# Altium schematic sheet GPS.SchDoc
size A3
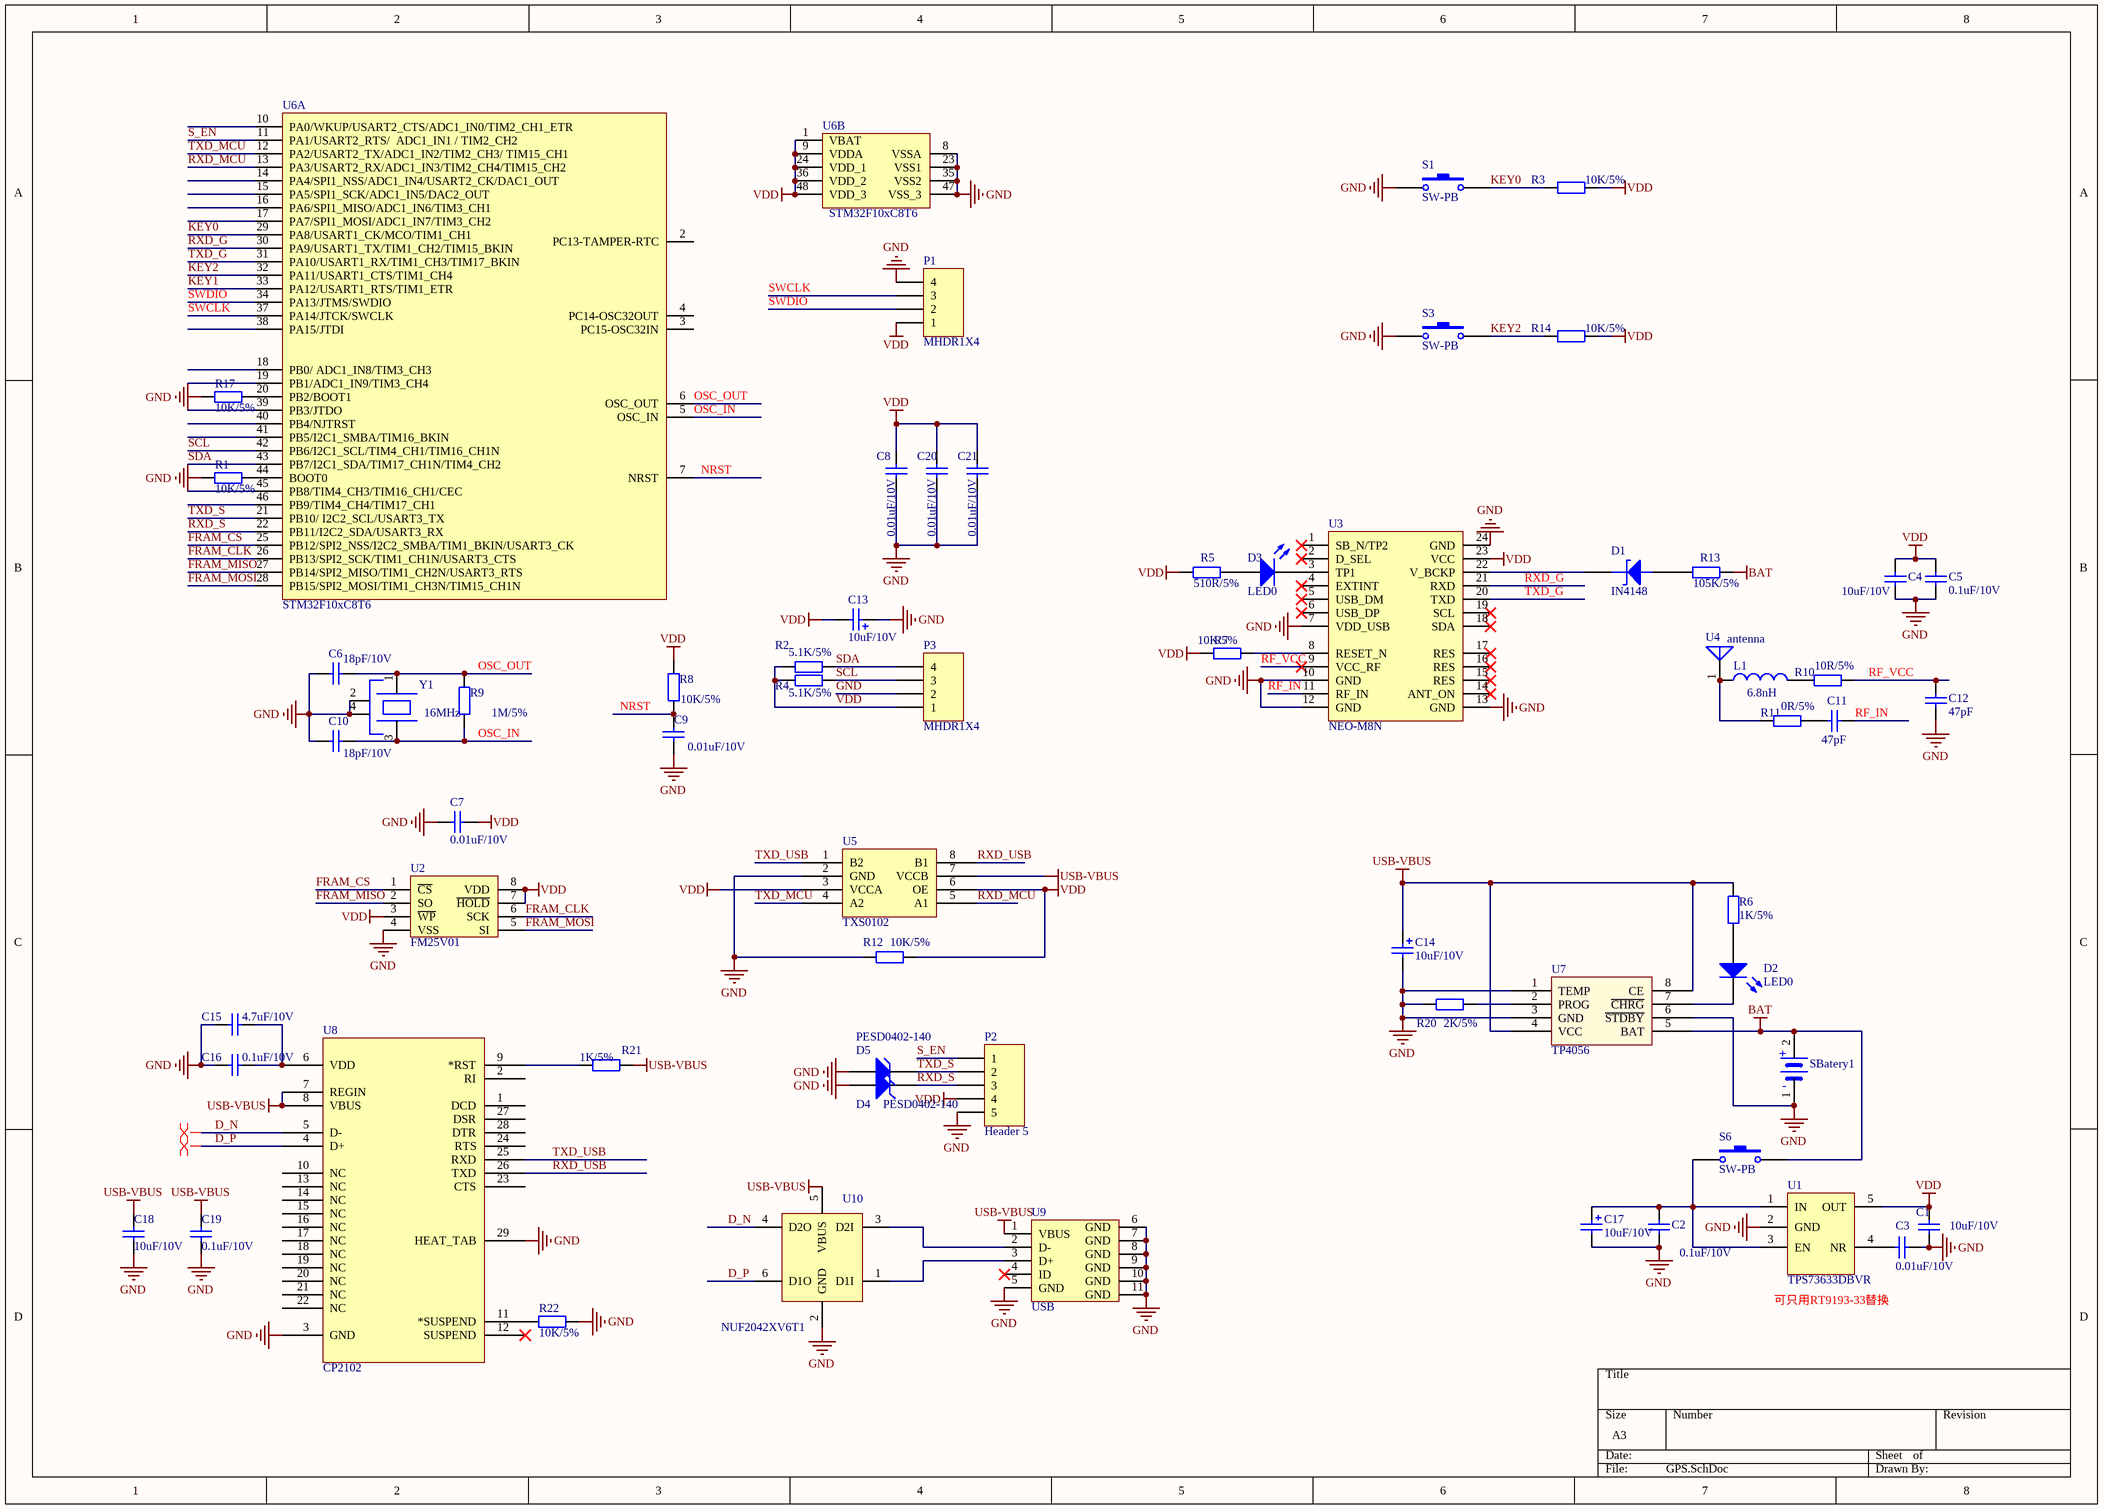
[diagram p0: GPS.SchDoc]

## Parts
C1  10uF/10V  [C0603]
C2  0.1uF/10V  [C0402]
C3  0.01uF/10V  [C0402]
C4  10uF/10V  [3528]
C5  0.1uF/10V  [C0402]
C6  18pF/10V  [C0402]
C7  0.01uF/10V  [C0402]
C8  0.01uF/10V  [C0402]
C9  0.01uF/10V  [C0402]
C10  18pF/10V  [C0402]
C11  value 47pF  [C0402]  (hidden comment: 470pF)
C12  value 47pF  [C0402]  (hidden comment: 33nF)
C13  10uF/10V  [C1206]
C14  10uF/10V  [3528]
C15  4.7uF/10V  [C0603]
C16  0.1uF/10V  [C0402]
C17  10uF/10V  [3528]
C18  10uF/10V  [C0603]
C19  0.1uF/10V  [C0402]
C20  0.01uF/10V  [C0402]
C21  0.01uF/10V  [C0402]
D1  IN4148  [L1206]
D2  LED0  [LED0603]
D3  LED0  [LED0603]
D4  PESD0402-140  [0402-TVS]
D5  PESD0402-140  [0402-TVS]
L1  6.8nH  [R0603]
P1  MHDR1X4  [SIP4_1.27]
P2  Header 5  [HDR1X5]
P3  MHDR1X4  [OLED]
R1  10K/5%  [R0402]
R2  5.1K/5%  [R0402]
R3  10K/5%  [R0402]
R4  5.1K/5%  [R0402]
R5  510R/5%  [R0402]
R6  1K/5%  [R0402]
R7  10K/5%  [R0402]
R8  10K/5%  [R0402]
R9  1M/5%  [R0402]
R10  10R/5%  [R0402]
R11  0R/5%  [R0402]
R12  10K/5%  [R0402]
R13  105K/5%  [R0402]
R14  10K/5%  [R0402]
R17  10K/5%  [R0402]
R20  2K/5%  [R0402]
R21  1K/5%  [R0402]
R22  10K/5%  [R0402]
S1  SW-PB  [KEY2]
S3  SW-PB  [KEY2]
S6  SW-PB  [KEY1]
SBatery1  SBatery  [SIP2]  (value not drawn)
U1  TPS73633DBVR  [SOP5-TPS73633DBVR]
U2  FM25V01  [SO-8]
U3  NEO-M8N  [NEO-M8N]
U4  antenna  [Active antenna]
U5  TXS0102  [R-PDSO-G8]
U6  STM32F10xC8T6  [LQFP-48]  (parts A,B of 2)
U7  TP4056  [SO-8-1]
U8  CP2102  [QFN-28]
U9  USB  [MOLEX-47346-0001]
U10  NUF2042XV6T1  [UDFN]
Y1  16MHz  [OSCILLATOR-3.2X2.5]

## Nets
BAT: R13.2 S6.2 SBatery1.2 U7.5(BAT)
GND: C1.1 C2.2 C3.2 C4.2 C5.2 C6.1 C7.2 C8.2 C9.1 C10.1 C12.1 C13.1 C14.2 C15.1 C16.2 C17.2 C18.2 C19.2 C20.2 C21.2 D4.1(A) D5.1(A) P1.4 P2.5 P3.2 R1.2 R12.2 R17.2 R20.1 R22.2 S1.1 S3.1 SBatery1.1 U1.2(GND) U2.4(VSS) U3.7(VDD_USB) U3.10(GND) U3.12(GND) U3.13(GND) U3.24(GND) U5.2(GND) U6.8(VSSA) U6.23(VSS1) U6.35(VSS2) U6.47(VSS_3) U7.1(TEMP) U7.3(GND) U7.6(~{STDBY}) U8.3(GND) U8.29(HEAT_TAB) U9.5(GND) U9.6(GND) U9.7(GND) U9.8(GND) U9.9(GND) U9.10(GND) U9.11(GND) U10.2(GND) Y1.2(GND) Y1.4(GND)
USB-VBUS: C14.1 C18.1 C19.1 R6.1 R21.2 U5.7(VCCB) U7.4(VCC) U7.8(CE) U8.7(REGIN) U8.8(VBUS) U9.1(VBUS) U10.5(VBUS)
VDD: C1.2 C4.1 C5.1 C7.1 C8.1 C13.2 C20.1 C21.1 P1.1 P2.4 P3.1 R2.2 R3.1 R4.2 R5.1 R7.2 R8.2 R12.1 R14.1 U1.5(OUT) U2.3(~{WP}) U2.7(~{HOLD}) U2.8(VDD) U3.23(VCC) U5.3(VCCA) U5.6(OE) U6.1(VBAT) U6.9(VDDA) U6.24(VDD_1) U6.36(VDD_2) U6.48(VDD_3)
D_N: U8.5(D-) U10.4(D2O)
D_P: U8.4(D+) U10.6(D1O)
FRAM_CLK: U2.6(SCK) U6.26(PB13/SPI2_SCK/TIM1_CH1N/USART3_CTS)
FRAM_CS: U2.1(~{CS}) U6.25(PB12/SPI2_NSS/I2C2_SMBA/TIM1_BKIN/USART3_CK)
FRAM_MISO: U2.2(SO) U6.27(PB14/SPI2_MISO/TIM1_CH2N/USART3_RTS)
FRAM_MOSI: U2.5(SI) U6.28(PB15/SPI2_MOSI/TIM1_CH3N/TIM15_CH1N)
KEY0: R3.2 S1.2 U6.29(PA8/USART1_CK/MCO/TIM1_CH1)
KEY1: U6.33(PA12/USART1_RTS/TIM1_ETR)
KEY2: R14.2 S3.2 U6.32(PA11/USART1_CTS/TIM1_CH4)
NRST: C9.2 R8.1 U6.7(NRST)
OSC_IN: C10.2 R9.1 U6.5(OSC_IN) Y1.3
OSC_OUT: C6.2 R9.2 U6.6(OSC_OUT) Y1.1
RF_IN: C11.2 U3.11(RF_IN)
RF_VCC: C12.2 R10.1 U3.9(VCC_RF)
RXD_G: U3.21(RXD) U6.30(PA9/USART1_TX/TIM1_CH2/TIM15_BKIN)
RXD_MCU: U5.5(A1) U6.13(PA3/USART2_RX/ADC1_IN3/TIM2_CH4/TIM15_CH2)
RXD_S: D4.2(K) P2.3 U6.22(PB11/I2C2_SDA/USART3_RX)
RXD_USB: U5.8(B1) U8.26(TXD)
S_EN: P2.1 U6.11(PA1/USART2_RTS/__ADC1_IN1_/_TIM2_CH2)
SCL: P3.3 R4.1 U6.42(PB6/I2C1_SCL/TIM4_CH1/TIM16_CH1N)
SDA: P3.4 R2.1 U6.43(PB7/I2C1_SDA/TIM17_CH1N/TIM4_CH2)
SWCLK: P1.3 U6.37(PA14/JTCK/SWCLK)
SWDIO: P1.2 U6.34(PA13/JTMS/SWDIO)
TXD_G: U3.20(TXD) U6.31(PA10/USART1_RX/TIM1_CH3/TIM17_BKIN)
TXD_MCU: U5.4(A2) U6.12(PA2/USART2_TX/ADC1_IN2/TIM2_CH3/_TIM15_CH1)
TXD_S: D5.2(K) P2.2 U6.21(PB10/_I2C2_SCL/USART3_TX)
TXD_USB: U5.1(B2) U8.25(RXD)
NetC2_1: C2.1 C17.1 S6.1 U1.1(IN) U1.3(EN)
NetC3_1: C3.1 U1.4(NR)
NetC11_1: C11.1 R11.1
NetC15_2: C15.2 C16.1 U8.6(VDD)
NetD1_1: D1.1(A) R13.1
NetD1_2: D1.2(K) U3.22(V_BCKP)
NetD2_1: D2.1(A) R6.2
NetD2_2: D2.2(K) U7.7(~{CHRG})
NetD3_1: D3.1(A) R5.2
NetD3_2: D3.2(K) U3.3(TP1)
NetL1_1: L1.1 R11.2 U4.1
NetL1_2: L1.2 R10.2
NetR1_1: R1.1 U6.44(BOOT0)
NetR7_1: R7.1 U3.8(RESET_N)
NetR17_1: R17.1 U6.20(PB2/BOOT1)
NetR20_2: R20.2 U7.2(PROG)
NetR21_1: R21.1 U8.9(*RST)
NetR22_1: R22.1 U8.11(*SUSPEND)
NetU9_2: U9.2(D-) U10.3(D2I)
NetU9_3: U9.3(D+) U10.1(D1I)

Not connected (* = marked no-connect by the designer): U3 1(SB_N/TP2)* 2(D_SEL)* 4(EXTINT)* 5(USB_DM)* 6(USB_DP)* 14(ANT_ON)* 15(RES)* 16(RES)* 17(RES)* 18(SDA)* 19(SCL)*; U6 2(PC13-TAMPER-RTC) 3(PC15-OSC32IN) 4(PC14-OSC32OUT) 10(PA0/WKUP/USART2_CTS/ADC1_IN0/TIM2_CH1_ETR) 14(PA4/SPI1_NSS/ADC1_IN4/USART2_CK/DAC1_OUT) 15(PA5/SPI1_SCK/ADC1_IN5/DAC2_OUT) 16(PA6/SPI1_MISO/ADC1_IN6/TIM3_CH1) 17(PA7/SPI1_MOSI/ADC1_IN7/TIM3_CH2) 18(PB0/_ADC1_IN8/TIM3_CH3) 19(PB1/ADC1_IN9/TIM3_CH4) 38(PA15/JTDI) 39(PB3/JTDO) 40(PB4/NJTRST) 41(PB5/I2C1_SMBA/TIM16_BKIN) 45(PB8/TIM4_CH3/TIM16_CH1/CEC) 46(PB9/TIM4_CH4/TIM17_CH1); U8 1(DCD) 2(RI) 10(NC) 12(SUSPEND)* 13(NC) 14(NC) 15(NC) 16(NC) 17(NC) 18(NC) 19(NC) 20(NC) 21(NC) 22(NC) 23(CTS) 24(RTS) 27(DSR) 28(DTR); U9 4(ID)*

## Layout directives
differential pair: D_N, D_P

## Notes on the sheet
- 可只用RT9193-33替换

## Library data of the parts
C1-C6 C10-C12 = Cap: Capacitor
C7 C8 C20 C21 = Cap: Capacitor; Value: 106
C9 C15 C16 C18 C19 = Cap: Capacitor; Value: 1uF
C13 C14 C17 = Cap Pol2: Polarized Capacitor (Axial)
D1 = ZENER2: Zener Diode
D2 D3 = LED0: Typical INFRARED GaAs LED
D4 D5 = D Zener: Zener Diode
L1 = Inductor: Code_IEC: 1005
P1 P3 = MHDR1X4: Header, 4-Pin
P2 = Header 5: Header, 5-Pin
R1 R3 R9 R14 R17 = Res2: Resistor; Value: 10K
R2 R4 R5 R7 R8 R12 R13 = Res2: Resistor
R6 R20 = Res2: Resistor; Value: 1K
R10 = Res2: Resistor; Value: 10R
R11 = Res2: Resistor; Value: 0R
R21 R22 = Resistor: Resistor SMD - IEC symbol version; Value: NC
S1 S3 S6 = SW-PB: Switch
U2 = FM25CL64B
U6 = STM32F100C8T6
U8 = CP2102: Imported; PART DESC: SINGLE-CHIP USB TO UART BRIDGE, QFN28, RoHS.; MFG #1: SILICON LABS
U9 = MICRO_USB
Y1 = XTAL3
